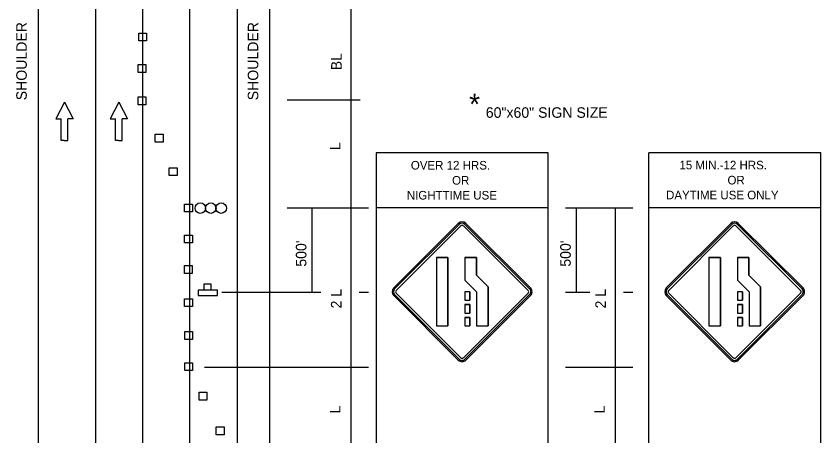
# Model space of a CAD drawing. Extents: x 15310.1 to 15319.5, y 15309 to 15319.1.
# Drawn here: x 15314.672 to 15319.257, y 15314.35 to 15316.744 of the extents above; entities that cross this region are included whole.
import ezdxf

# ---------------------------------------------------------------- set-up
doc = ezdxf.new("R2010")
doc.units = 0
for name, color, linetype in [('DETL-DIMS', 7, 'Continuous'), ('DETL-LINE', 7, 'Continuous'), ('DETL-NOTE', 7, 'Continuous'), ('USER-BORD', 7, 'Continuous')]:
    doc.layers.add(name, color=color, linetype=linetype)

# ---------------------------------------------------------------- blocks, each defined once
blk = doc.blocks.new('CD4')
at = {"layer": 'USER-BORD'}
blk.add_lwpolyline([(0, 0.031), (0.031, 0.031), (0.031, 0), (0, 0)], close=True, dxfattribs=at)
blk = doc.blocks.new('PANEL0')
at = {"layer": 'USER-BORD'}
for centre in [(0.0309, -0.0012), (0.0928, -0.0012), (0.1546, -0.0012)]:
    blk.add_circle(centre, 0.0312, dxfattribs=at)
blk = doc.blocks.new('DIR4')
at = {"layer": 'USER-BORD'}
for p, q in [((0, 0.001), (-0.034, -0.048)), ((0, 0.001), (0.034, -0.048)), ((-0.034, -0.048), (-0.013, -0.048)), ((-0.013, -0.113), (-0.013, -0.048)), ((0.034, -0.048), (0.013, -0.048)), ((0.013, -0.113), (0.013, -0.048)), ((-0.001, -0.113), (-0.013, -0.113)), ((-0.001, -0.113), (0.001, -0.113)), ((0.001, -0.113), (0.013, -0.113))]:
    blk.add_line(p, q, dxfattribs=at)
blk = doc.blocks.new('SIGN15')
at = {"layer": 'USER-BORD'}
for points in [[(-0.013, 0.018), (0.011, 0.019), (0.011, 0.037), (-0.013, 0.037)], [(-0.031, 0.018), (-0.031, 0), (0.032, 0), (0.032, 0.018)]]:
    blk.add_lwpolyline(points, close=True, dxfattribs=at)

msp = doc.modelspace()

# ---------------------------------------------------------------- linework, layer by layer
at = {"layer": 'DETL-DIMS'}
for p, q in [((15316.579, 15316.805), (15316.579, 15314.742)), ((15316.216, 15316.266), (15316.632, 15316.266)), ((15316.216, 15315.651), (15316.68, 15315.65)), ((15316.356, 15315.65), (15316.356, 15315.17)), ((15317.803, 15315.65), (15318.185, 15315.65)), ((15317.862, 15315.65), (15317.862, 15315.17)), ((15318.085, 15315.65), (15318.085, 15314.742)), ((15315.8448, 15315.1701), (15316.4086, 15315.1701)), ((15316.626, 15315.1701), (15316.679, 15315.1701)), ((15317.803, 15315.17), (15317.941, 15315.17)), ((15318.1324, 15315.1701), (15318.1854, 15315.1701)), ((15315.746, 15314.742), (15316.679, 15314.742)), ((15316.579, 15314.742), (15316.579, 15314.211)), ((15317.803, 15314.742), (15318.185, 15314.742)), ((15318.0854, 15314.742), (15318.0854, 15314.211))]:
    msp.add_line(p, q, dxfattribs=at)
at = {"layer": 'DETL-LINE'}
for p, q in [((15315.126, 15310.865), (15315.126, 15318.5087)), ((15315.394, 15310.865), (15315.394, 15318.5087)), ((15315.662, 15310.865), (15315.662, 15318.5087)), ((15314.797, 15318.4337), (15314.797, 15310.79)), ((15315.932, 15318.4337), (15315.932, 15310.79)), ((15316.115, 15318.4337), (15316.115, 15310.79)), ((15316.724, 15315.9643), (15316.724, 15310.5092)), ((15317.704, 15315.9643), (15316.724, 15315.9643)), ((15317.704, 15310.5092), (15317.704, 15315.9643)), ((15318.2772, 15311.4043), (15318.2772, 15315.9643)), ((15319.2571, 15315.9643), (15318.2772, 15315.9643)), ((15319.2571, 15311.4043), (15319.2571, 15315.9643)), ((15317.704, 15315.6497), (15316.724, 15315.6497)), ((15319.2571, 15315.6497), (15318.2772, 15315.6497)), ((15316.8234, 15315.1935), (15317.1915, 15315.5617)), ((15316.8288, 15315.1881), (15317.1969, 15315.5562)), ((15316.8373, 15315.1796), (15317.2055, 15315.5477)), ((15317.2202, 15315.5477), (15317.5891, 15315.1796)), ((15317.2287, 15315.5562), (15317.5976, 15315.1881)), ((15317.2341, 15315.5617), (15317.603, 15315.1935)), ((15318.3759, 15315.1935), (15318.7441, 15315.5617)), ((15318.3814, 15315.1881), (15318.7495, 15315.5562)), ((15318.3899, 15315.1796), (15318.758, 15315.5477)), ((15318.7727, 15315.5477), (15319.1416, 15315.1796)), ((15318.7813, 15315.5562), (15319.1502, 15315.1881)), ((15318.7867, 15315.5617), (15319.1556, 15315.1935)), ((15317.0664, 15315.3676), (15317.0664, 15314.9769)), ((15317.0664, 15315.3676), (15317.132, 15315.3676)), ((15317.132, 15315.3676), (15317.0664, 15315.3676)), ((15317.0664, 15315.3676), (15317.0664, 15314.9769)), ((15317.132, 15315.3676), (15317.132, 15314.9769)), ((15317.132, 15314.9769), (15317.132, 15315.3676)), ((15317.2289, 15315.3676), (15317.2289, 15315.2386)), ((15317.2289, 15315.3676), (15317.2945, 15315.3676)), ((15317.2945, 15315.3676), (15317.2289, 15315.3676)), ((15317.2289, 15315.3676), (15317.2289, 15315.2386)), ((15317.2945, 15315.3676), (15317.2945, 15315.2658)), ((15317.2945, 15315.2658), (15317.2945, 15315.3676)), ((15318.6189, 15315.3676), (15318.6189, 15314.9769)), ((15318.6189, 15315.3676), (15318.6845, 15315.3676)), ((15318.6845, 15315.3676), (15318.6189, 15315.3676)), ((15318.6189, 15315.3676), (15318.6189, 15314.9769)), ((15318.6845, 15315.3676), (15318.6845, 15314.9769)), ((15318.6845, 15314.9769), (15318.6845, 15315.3676)), ((15318.7815, 15315.3676), (15318.7815, 15315.2386)), ((15318.7815, 15315.3676), (15318.8471, 15315.3676)), ((15318.8471, 15315.3676), (15318.7815, 15315.3676)), ((15318.7815, 15315.3676), (15318.7815, 15315.2386)), ((15318.8471, 15315.3676), (15318.8471, 15315.2658)), ((15318.8471, 15315.2658), (15318.8471, 15315.3676)), ((15317.3609, 15315.1994), (15317.2945, 15315.2658)), ((15317.3609, 15315.1994), (15317.2945, 15315.2658)), ((15318.9135, 15315.1994), (15318.8471, 15315.2658)), ((15318.9135, 15315.1994), (15318.8471, 15315.2658)), ((15317.2953, 15315.1722), (15317.2289, 15315.2386)), ((15317.2289, 15315.2386), (15317.2953, 15315.1722)), ((15318.8479, 15315.1722), (15318.7815, 15315.2386)), ((15318.7815, 15315.2386), (15318.8479, 15315.1722)), ((15317.2055, 15314.796), (15316.8373, 15315.1649)), ((15317.5891, 15315.1649), (15317.2202, 15314.796)), ((15317.2289, 15315.1722), (15317.2289, 15315.1234)), ((15317.2579, 15315.1722), (15317.2289, 15315.1722)), ((15317.2289, 15315.1722), (15317.2289, 15315.1234)), ((15317.2579, 15315.1722), (15317.2579, 15315.1234)), ((15317.2579, 15315.1234), (15317.2579, 15315.1722)), ((15317.2953, 15315.1722), (15317.2953, 15314.9769)), ((15317.2953, 15315.1722), (15317.2953, 15314.9769)), ((15317.3609, 15315.1994), (15317.3609, 15314.9769)), ((15317.3609, 15314.9769), (15317.3609, 15315.1994)), ((15318.758, 15314.796), (15318.3899, 15315.1649)), ((15319.1416, 15315.1649), (15318.7727, 15314.796)), ((15318.7815, 15315.1722), (15318.7815, 15315.1234)), ((15318.8105, 15315.1722), (15318.7815, 15315.1722)), ((15318.7815, 15315.1722), (15318.7815, 15315.1234)), ((15318.8105, 15315.1722), (15318.8105, 15315.1234)), ((15318.8105, 15315.1234), (15318.8105, 15315.1722)), ((15318.8479, 15315.1722), (15318.8479, 15314.9769)), ((15318.8479, 15315.1722), (15318.8479, 15314.9769)), ((15318.9135, 15315.1994), (15318.9135, 15314.9769)), ((15318.9135, 15314.9769), (15318.9135, 15315.1994)), ((15317.1915, 15314.782), (15316.8234, 15315.1509)), ((15317.1969, 15314.7874), (15316.8288, 15315.1563)), ((15317.5976, 15315.1563), (15317.2287, 15314.7874)), ((15317.2289, 15315.1234), (15317.2579, 15315.1234)), ((15317.2289, 15315.1234), (15317.2579, 15315.1234)), ((15317.603, 15315.1509), (15317.2341, 15314.782)), ((15318.7441, 15314.782), (15318.3759, 15315.1509)), ((15318.7495, 15314.7874), (15318.3814, 15315.1563)), ((15319.1502, 15315.1563), (15318.7813, 15314.7874)), ((15318.7815, 15315.1234), (15318.8105, 15315.1234)), ((15318.7815, 15315.1234), (15318.8105, 15315.1234)), ((15319.1556, 15315.1509), (15318.7867, 15314.782)), ((15317.2289, 15315.099), (15317.2579, 15315.099)), ((15317.2289, 15315.099), (15317.2289, 15315.0502)), ((15317.2579, 15315.099), (15317.2289, 15315.099)), ((15317.2289, 15315.099), (15317.2289, 15315.0502)), ((15317.2579, 15315.099), (15317.2579, 15315.0502)), ((15317.2579, 15315.0502), (15317.2579, 15315.099)), ((15318.7815, 15315.099), (15318.8105, 15315.099)), ((15318.7815, 15315.099), (15318.7815, 15315.0502)), ((15318.8105, 15315.099), (15318.7815, 15315.099)), ((15318.7815, 15315.099), (15318.7815, 15315.0502)), ((15318.8105, 15315.099), (15318.8105, 15315.0502)), ((15318.8105, 15315.0502), (15318.8105, 15315.099)), ((15317.2289, 15315.0502), (15317.2579, 15315.0502)), ((15317.2289, 15315.0502), (15317.2579, 15315.0502)), ((15317.2289, 15315.0257), (15317.2579, 15315.0257)), ((15317.2289, 15315.0257), (15317.2289, 15314.9769)), ((15317.2579, 15315.0257), (15317.2289, 15315.0257)), ((15317.2289, 15315.0257), (15317.2289, 15314.9769)), ((15317.2579, 15315.0257), (15317.2579, 15314.9769)), ((15317.2579, 15314.9769), (15317.2579, 15315.0257)), ((15318.7815, 15315.0502), (15318.8105, 15315.0502)), ((15318.7815, 15315.0502), (15318.8105, 15315.0502)), ((15318.7815, 15315.0257), (15318.8105, 15315.0257)), ((15318.7815, 15315.0257), (15318.7815, 15314.9769)), ((15318.8105, 15315.0257), (15318.7815, 15315.0257)), ((15318.7815, 15315.0257), (15318.7815, 15314.9769)), ((15318.8105, 15315.0257), (15318.8105, 15314.9769)), ((15318.8105, 15314.9769), (15318.8105, 15315.0257)), ((15317.0664, 15314.9769), (15317.132, 15314.9769)), ((15317.0664, 15314.9769), (15317.132, 15314.9769)), ((15317.2289, 15314.9769), (15317.2579, 15314.9769)), ((15317.2289, 15314.9769), (15317.2579, 15314.9769)), ((15317.2953, 15314.9769), (15317.3609, 15314.9769)), ((15317.2953, 15314.9769), (15317.3609, 15314.9769)), ((15318.6189, 15314.9769), (15318.6845, 15314.9769)), ((15318.6189, 15314.9769), (15318.6845, 15314.9769)), ((15318.7815, 15314.9769), (15318.8105, 15314.9769)), ((15318.7815, 15314.9769), (15318.8105, 15314.9769)), ((15318.8479, 15314.9769), (15318.9135, 15314.9769)), ((15318.8479, 15314.9769), (15318.9135, 15314.9769))]:
    msp.add_line(p, q, dxfattribs=at)
for points in [[(15315.126, 15316.265), (15315.126, 15316.34)], [(15315.394, 15316.265), (15315.394, 15316.34)], [(15315.126, 15316.19), (15315.126, 15316.265)], [(15315.394, 15316.19), (15315.394, 15316.265)], [(15315.126, 15315.665), (15315.126, 15315.74)], [(15315.126, 15315.59), (15315.126, 15315.665)], [(15315.126, 15315.065), (15315.126, 15315.14)], [(15315.394, 15315.065), (15315.394, 15315.14)], [(15315.126, 15314.99), (15315.126, 15315.065)], [(15315.394, 15314.99), (15315.394, 15315.065)], [(15315.126, 15314.465), (15315.126, 15314.54)], [(15315.394, 15314.465), (15315.394, 15314.54)], [(15315.126, 15314.39), (15315.126, 15314.465)], [(15315.394, 15314.39), (15315.394, 15314.465)]]:
    msp.add_lwpolyline(points, dxfattribs=at)
for centre, radius, start, end in [((15317.2128, 15315.5402), 0.0303, 45.06, 135), ((15317.2128, 15315.5406), 0.0223, 45.06, 135), ((15317.2128, 15315.5408), 0.0101, 45.06, 135), ((15318.7654, 15315.5402), 0.0303, 45.06, 135), ((15318.7654, 15315.5406), 0.0223, 45.06, 135), ((15318.7654, 15315.5408), 0.0101, 45.06, 135), ((15316.8449, 15315.1722), 0.0303, 135, 224.9399), ((15316.8444, 15315.1722), 0.0223, 135, 224.9399), ((15316.8442, 15315.1722), 0.0101, 135, 224.9399), ((15317.5822, 15315.1722), 0.0101, 315, 45.0601), ((15317.582, 15315.1722), 0.0223, 315, 45.0601), ((15317.5815, 15315.1722), 0.0303, 315, 45.0601), ((15318.3974, 15315.1722), 0.0303, 135, 224.9399), ((15318.397, 15315.1722), 0.0223, 135, 224.9399), ((15318.3968, 15315.1722), 0.0101, 135, 224.9399), ((15319.1347, 15315.1722), 0.0101, 315, 45.0601), ((15319.1345, 15315.1722), 0.0223, 315, 45.0601), ((15319.1341, 15315.1722), 0.0303, 315, 45.0601), ((15317.2128, 15314.8035), 0.0303, 224.94, 315), ((15317.2128, 15314.8031), 0.0223, 224.94, 315), ((15317.2128, 15314.8029), 0.0101, 224.94, 315), ((15318.7654, 15314.8035), 0.0303, 224.94, 315), ((15318.7654, 15314.8031), 0.0223, 224.94, 315), ((15318.7654, 15314.8029), 0.0101, 224.94, 315)]:
    msp.add_arc(centre, radius, start, end, dxfattribs=at)

# ---------------------------------------------------------------- block references
for name, p, xscale, yscale in [('CD4', (15315.371, 15316.602), 1.4400000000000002, 1.4400000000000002), ('CD4', (15315.367, 15316.423), 1.4400000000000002, 1.4400000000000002), ('CD4', (15315.367, 15316.238), 1.4400000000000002, 1.4400000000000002), ('DIR4', (15314.948, 15316.251), 1.4400000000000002, 1.9200000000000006), ('DIR4', (15315.257, 15316.251), 1.4400000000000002, 1.9200000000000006), ('CD4', (15315.465, 15316.026), 1.4400000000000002, 1.4400000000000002), ('CD4', (15315.545, 15315.835), 1.4400000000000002, 1.4400000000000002), ('CD4', (15315.632, 15315.627), 1.4400000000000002, 1.4400000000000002), ('PANEL0', (15315.692, 15315.65), 0.9600000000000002, 0.9600000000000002), ('CD4', (15315.632, 15315.451), 1.4400000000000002, 1.4400000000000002), ('CD4', (15315.631, 15315.277), 1.4400000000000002, 1.4400000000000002), ('SIGN15', (15315.764, 15315.15), 1.7523809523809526, 1.7523809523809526), ('CD4', (15315.632, 15315.088), 1.4400000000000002, 1.4400000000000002), ('CD4', (15315.633, 15314.9), 1.4400000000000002, 1.4400000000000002), ('CD4', (15315.633, 15314.723), 1.4400000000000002, 1.4400000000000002), ('CD4', (15315.715, 15314.554), 1.4400000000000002, 1.4400000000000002), ('CD4', (15315.812, 15314.357), 1.4400000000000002, 1.4400000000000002)]:
    msp.add_blockref(name, p, dxfattribs=dict(at, xscale=xscale, yscale=yscale))

# ---------------------------------------------------------------- texts
for s, height, p in [('OVER 12 HRS.', 0.049002, (15316.921, 15315.869)), ('15 MIN.-12 HRS.', 0.049002, (15318.451, 15315.87)), ('OR', 0.049, (15317.156, 15315.783)), ('OR', 0.049, (15318.725, 15315.784)), ('NIGHTTIME USE', 0.049002, (15316.898, 15315.698)), ('DAYTIME USE ONLY', 0.049002, (15318.375, 15315.699))]:
    msp.add_text(s, height=height, dxfattribs=at).set_placement(p)
at = {"layer": 'DETL-NOTE'}
for s, p in [('SHOULDER', (15314.733, 15316.264)), ('SHOULDER', (15316.052, 15316.264)), ('BL', (15316.527, 15316.435)), ('L', (15316.52, 15315.98)), ("500'", (15316.326, 15315.315)), ("500'", (15317.832, 15315.315)), ('2 L', (15316.526, 15315.077)), ('2 L', (15318.032, 15315.077)), ('L', (15316.52, 15314.478)), ('L', (15318.026, 15314.478))]:
    msp.add_text(s, height=0.06, rotation=90, dxfattribs=at).set_placement(p)
for s, height, p in [('*', 0.12, (15317.253, 15316.182)), ('60"x60" SIGN SIZE', 0.06, (15317.348, 15316.164))]:
    msp.add_text(s, height=height, dxfattribs=at).set_placement(p)

doc.saveas('drawing.dxf')
